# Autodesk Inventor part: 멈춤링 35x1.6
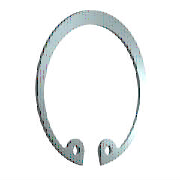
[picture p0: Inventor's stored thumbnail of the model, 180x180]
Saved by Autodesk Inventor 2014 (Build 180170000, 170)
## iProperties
IsCustomPart: 1
Created: 2015-09
Part Number: 멈춤링 35x1.6
Material: 강철, 연강
Description: 리테이닝 링(C형)
Document SubType Name: Modeling
Standard: KS B 1336
Designer: mduedu
Standards Organization: KS
Language: ko-KR
Size Designation: 35x1.6
Categories: <MemberInstance><Categories><Category DisplayName="샤프트 부품" InternalName="7f7aeb1f-a693-4053-b835-cee3144e0d98" Mnemonic="SHFT"><Category DisplayName="써클립" Inter
Density: 7.86 g/cm^3
Mass: 3.5371 g
Surface Area: 9.09651 cm^2
Volume: 0.450013 cm^3
Appearance: 파란색 - 벽 페인트 - 광택
Author: mduedu
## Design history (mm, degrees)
sketch "스케치1"
  geometry: L1 (0, 15.113)-(0, -73.177) reference; L2 (-45.5, 0)-(45.5, 0) reference; L3 (-4.964, 1)-(1.502, 1); L4 (0, -2.5)-(-5.307, -2.5); L5 (0, -17.5)-(-8.583, -33.888); L6 (-8.583, -33.888)-(-21.772, -26.981); L7 (-7.377, -31.585)-(-17.631, -26.214); L8 (-5.162, -32.745)-(-6.29, -34.898); L9 (5.162, -32.745)-(6.29, -34.898); C1 r 1.25 at (-7.377, -31.585); C2 r 1.25 at (7.377, -31.585); A1 r 15.875 centre (0, -18.375) between (11.82, -28.972) and (-11.82, -28.972); A2 r 18.5 centre (0, -17.5) between (6.29, -34.898) and (-6.29, -34.898); A3 r 2.5 centre (-7.377, -31.585) between (-5.162, -32.745) and (-8.668, -29.444); A4 r 2.5 centre (-9.959, -27.303) between (-11.82, -28.972) and (-8.668, -29.444); A5 r 2.5 centre (9.959, -27.303) between (8.668, -29.444) and (11.82, -28.972); A6 r 2.5 centre (7.377, -31.585) between (8.668, -29.444) and (5.162, -32.745); 3 further points
  constraints: 15 point on circle, 14 end point, 9 symmetric about line, 8 centre point, 6 tangent, 4 coincident, 4 point on line, 3 perpendicular, 1 parallel, 4 other
  dimensions: "d8" = 0.875 distance of A1.centre L5.start (= 0.25 x SRB1); "d38" = 3.5 distance between parallel lines of L4 L3 (= SRB1); "d39" = 17.5 distance from line of L5.start L2 (= 0.5 x WD); "d43" = 18.5 radius of A2 (= 0.5 x ND); "d45" = 2.6 distance between parallel lines of L7 L6 (= 0.5 x SRB2); "d46" = 2.5 radius of A4 (= SD5); "d47" = 6.29 distance from line of L1 L8.end (= 0.17 x ND); "d48" = 2.5 diameter of C1 (= SD5); "d49" = 2.5 radius of A3 (= SD5)
extrude "본체" new body sketch "스케치1" distance "d2" = 1.6 (= SD); taper "d3" = 0 deg
workaxis "Work Axis1"
workaxis "Work Axis2"
workplane "Work Plane1"
body "Solid1"
other parameters: "WD" = 35 [user parameter; used in 3 equation terms], "SD" = 1.6 [user parameter; used in 1 equation term], "SRB1" = 3.5 [user parameter; used in 2 equation terms], "ND" = 37 [user parameter; used in 2 equation terms], "SRB2" = 5.2 [user parameter; used in 1 equation term], "SD5" = 2.5 [user parameter; used in 3 equation terms], "d50" = 0, "d51" = 0, "d52" = 0, "d53" = 0, "WDMIN" = 34 [user parameter], "SD6" = 37.8 [user parameter], "WDMAX" = 35 (= WD) [user parameter], "NND" = 35 (= WD) [user parameter]
